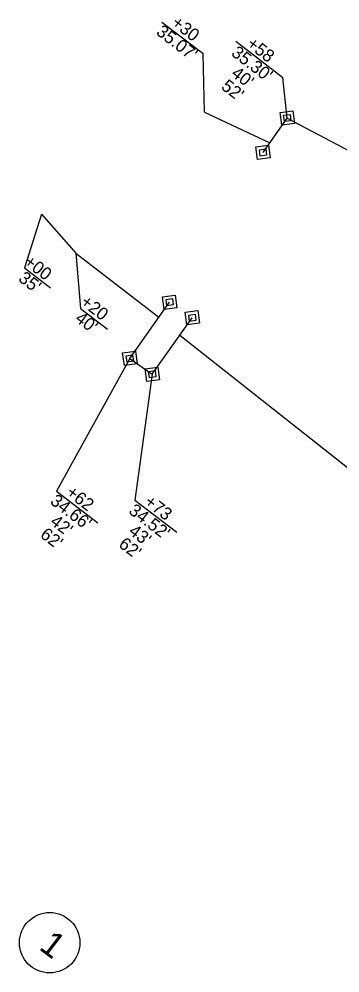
# Model space of a CAD drawing. Extents: x 1618217 to 1621927, y 897445 to 899141.
# Drawn here: x 1618772.6 to 1618899.8, y 898275.5 to 898654.5 of the extents above; entities that cross this region are included whole.
import ezdxf

# ---------------------------------------------------------------- set-up
doc = ezdxf.new("R2010")
doc.units = 0
for name, color, linetype in [('Prop Easement Construction', 7, 'Continuous'), ('Prop Easement Construction Station Offsets', 7, 'Continuous'), ('Prop Easement Permanent Utility', 7, 'Continuous'), ('Prop Easement Permanent Utility Station Offsets', 7, 'Continuous'), ('Prop Parcel Number CELL', 7, 'Continuous'), ('Prop ROW Marker CELL', 7, 'Continuous'), ('Prop ROW Permanent Easement CELL', 7, 'Continuous')]:
    doc.layers.add(name, color=color, linetype=linetype)

msp = doc.modelspace()

# ---------------------------------------------------------------- linework, layer by layer
at = {"layer": 'Prop Easement Construction'}
for p, q in [((1618846.03, 898617.46), (1618871.97, 898605.33)), ((1618781.49, 898576.9), (1618795.01, 898561.5)), ((1618795.01, 898561.5), (1618828.01, 898535.99)), ((1618836.34, 898528.88), (1619039.91, 898367.74))]:
    msp.add_line(p, q, dxfattribs=at)
at = {"layer": 'Prop Easement Construction Station Offsets'}
for p, q in [((1618829.18, 898653.29), (1618845.54, 898640.76)), ((1618846.03, 898617.46), (1618845.54, 898640.76)), ((1618781.49, 898576.9), (1618774.67, 898555.67)), ((1618795.01, 898561.5), (1618796.88, 898539.46)), ((1618774.67, 898555.67), (1618785.04, 898547.73)), ((1618796.88, 898539.46), (1618807.61, 898531.24))]:
    msp.add_line(p, q, dxfattribs=at)
at = {"layer": 'Prop Easement Permanent Utility'}
for p, q in [((1618869.27, 898601.48), (1618878.88, 898615.14)), ((1618878.88, 898615.14), (1619017.11, 898541.82)), ((1618816.48, 898519.65), (1618832.24, 898541.99)), ((1618825.35, 898513.38), (1618841.24, 898535.8)), ((1618816.48, 898519.65), (1618825.35, 898513.38))]:
    msp.add_line(p, q, dxfattribs=at)
at = {"layer": 'Prop Easement Permanent Utility Station Offsets'}
for p, q in [((1618858.43, 898645.66), (1618877.15, 898631.32)), ((1618878.88, 898615.14), (1618877.15, 898631.32)), ((1618816.48, 898519.65), (1618787.39, 898466.89)), ((1618825.35, 898513.38), (1618818.42, 898463.34)), ((1618787.39, 898466.89), (1618803.76, 898454.36)), ((1618818.42, 898463.34), (1618835.06, 898450.6))]:
    msp.add_line(p, q, dxfattribs=at)
at = {"layer": 'Prop Parcel Number CELL'}
msp.add_line((1618784.68, 898287.54), (1618784.68, 898287.54), dxfattribs=at)
msp.add_circle((1618784.68, 898287.54), 12, dxfattribs=at)
at = {"layer": 'Prop ROW Marker CELL'}
for p, q in [((1618878.88, 898615.14), (1618878.88, 898615.14)), ((1618869.27, 898601.48), (1618869.27, 898601.48)), ((1618832.24, 898541.99), (1618832.24, 898541.99)), ((1618841.24, 898535.8), (1618841.24, 898535.8)), ((1618816.48, 898519.65), (1618816.48, 898519.65)), ((1618825.35, 898513.38), (1618825.35, 898513.38))]:
    msp.add_line(p, q, dxfattribs=at)
at = {"layer": 'Prop ROW Permanent Easement CELL'}
for points in [[(1618881.07, 898618), (1618881.74, 898612.95), (1618876.69, 898612.28), (1618876.02, 898617.33)], [(1618879.98, 898616.57), (1618880.31, 898614.04), (1618877.79, 898613.71), (1618877.45, 898616.23)], [(1618871.46, 898604.34), (1618872.13, 898599.3), (1618867.08, 898598.63), (1618866.41, 898603.67)], [(1618870.36, 898602.91), (1618870.7, 898600.39), (1618868.17, 898600.06), (1618867.84, 898602.58)], [(1618834.43, 898544.85), (1618835.1, 898539.8), (1618830.05, 898539.14), (1618829.38, 898544.18)], [(1618833.34, 898543.42), (1618833.67, 898540.9), (1618831.15, 898540.56), (1618830.81, 898543.09)], [(1618843.43, 898538.66), (1618844.1, 898533.61), (1618839.05, 898532.94), (1618838.38, 898537.99)], [(1618842.34, 898537.23), (1618842.67, 898534.71), (1618840.15, 898534.37), (1618839.81, 898536.9)], [(1618818.67, 898522.51), (1618819.34, 898517.46), (1618814.29, 898516.79), (1618813.62, 898521.84)], [(1618817.58, 898521.08), (1618817.91, 898518.55), (1618815.39, 898518.22), (1618815.05, 898520.74)], [(1618827.54, 898516.24), (1618828.21, 898511.19), (1618823.16, 898510.52), (1618822.5, 898515.57)], [(1618826.45, 898514.81), (1618826.78, 898512.28), (1618824.26, 898511.95), (1618823.92, 898514.47)]]:
    msp.add_lwpolyline(points, close=True, dxfattribs=at)

# ---------------------------------------------------------------- texts
at = {"layer": 'Prop Easement Construction Station Offsets'}
for s, p in [('+30', (1618832.61, 898652.17)), ("35.07'", (1618826.55, 898648.63)), ('+00', (1618774.06, 898557.25)), ("35'", (1618771.92, 898550.7)), ('+20', (1618796.5, 898541.3)), ("40'", (1618794.37, 898534.75))]:
    msp.add_text(s, height=5, rotation=322.554, dxfattribs=at).set_placement(p)
at = {"layer": 'Prop Easement Permanent Utility Station Offsets'}
for s, p in [('+58', (1618862.38, 898643.82)), ("35.30'", (1618856.32, 898640.28)), ("40'", (1618856.29, 898632.11)), ("52'", (1618852.34, 898626.95)), ('+62', (1618790.8, 898465.61)), ("34.66'", (1618784.53, 898462.23)), ('+73', (1618821.79, 898461.87)), ("34.52'", (1618815.64, 898458.39)), ("42'", (1618784.5, 898454.06)), ("62'", (1618780.55, 898448.9)), ("43'", (1618815.61, 898450.23)), ("62'", (1618811.66, 898445.07))]:
    msp.add_text(s, height=5, rotation=322.554, dxfattribs=at).set_placement(p)
at = {"layer": 'Prop Parcel Number CELL'}
msp.add_text('1', height=10, rotation=322.554, dxfattribs=at).set_placement((1618780.05, 898285.21))

doc.saveas('drawing.dxf')
